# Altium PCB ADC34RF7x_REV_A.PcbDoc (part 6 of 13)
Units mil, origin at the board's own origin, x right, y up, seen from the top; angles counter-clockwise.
Board outline 6250 x 2716.54 mil, 18 copper layers (Top Layer, L2 GND, L3 PWR, L4 GND, L5 PWR/SIG, L6 GND, L7 SIGNAL, L8 GND, L9 GND, L10 SIGNAL, L11 GND, L12 SIGNAL, L13 GND, L14 PWR, L15 GND, L16 PWR/SIG, L16 GND, Bottom Layer), stack 95.314 mil thick; 668 components, 786 nets, 3150 pads, 2020 vias.
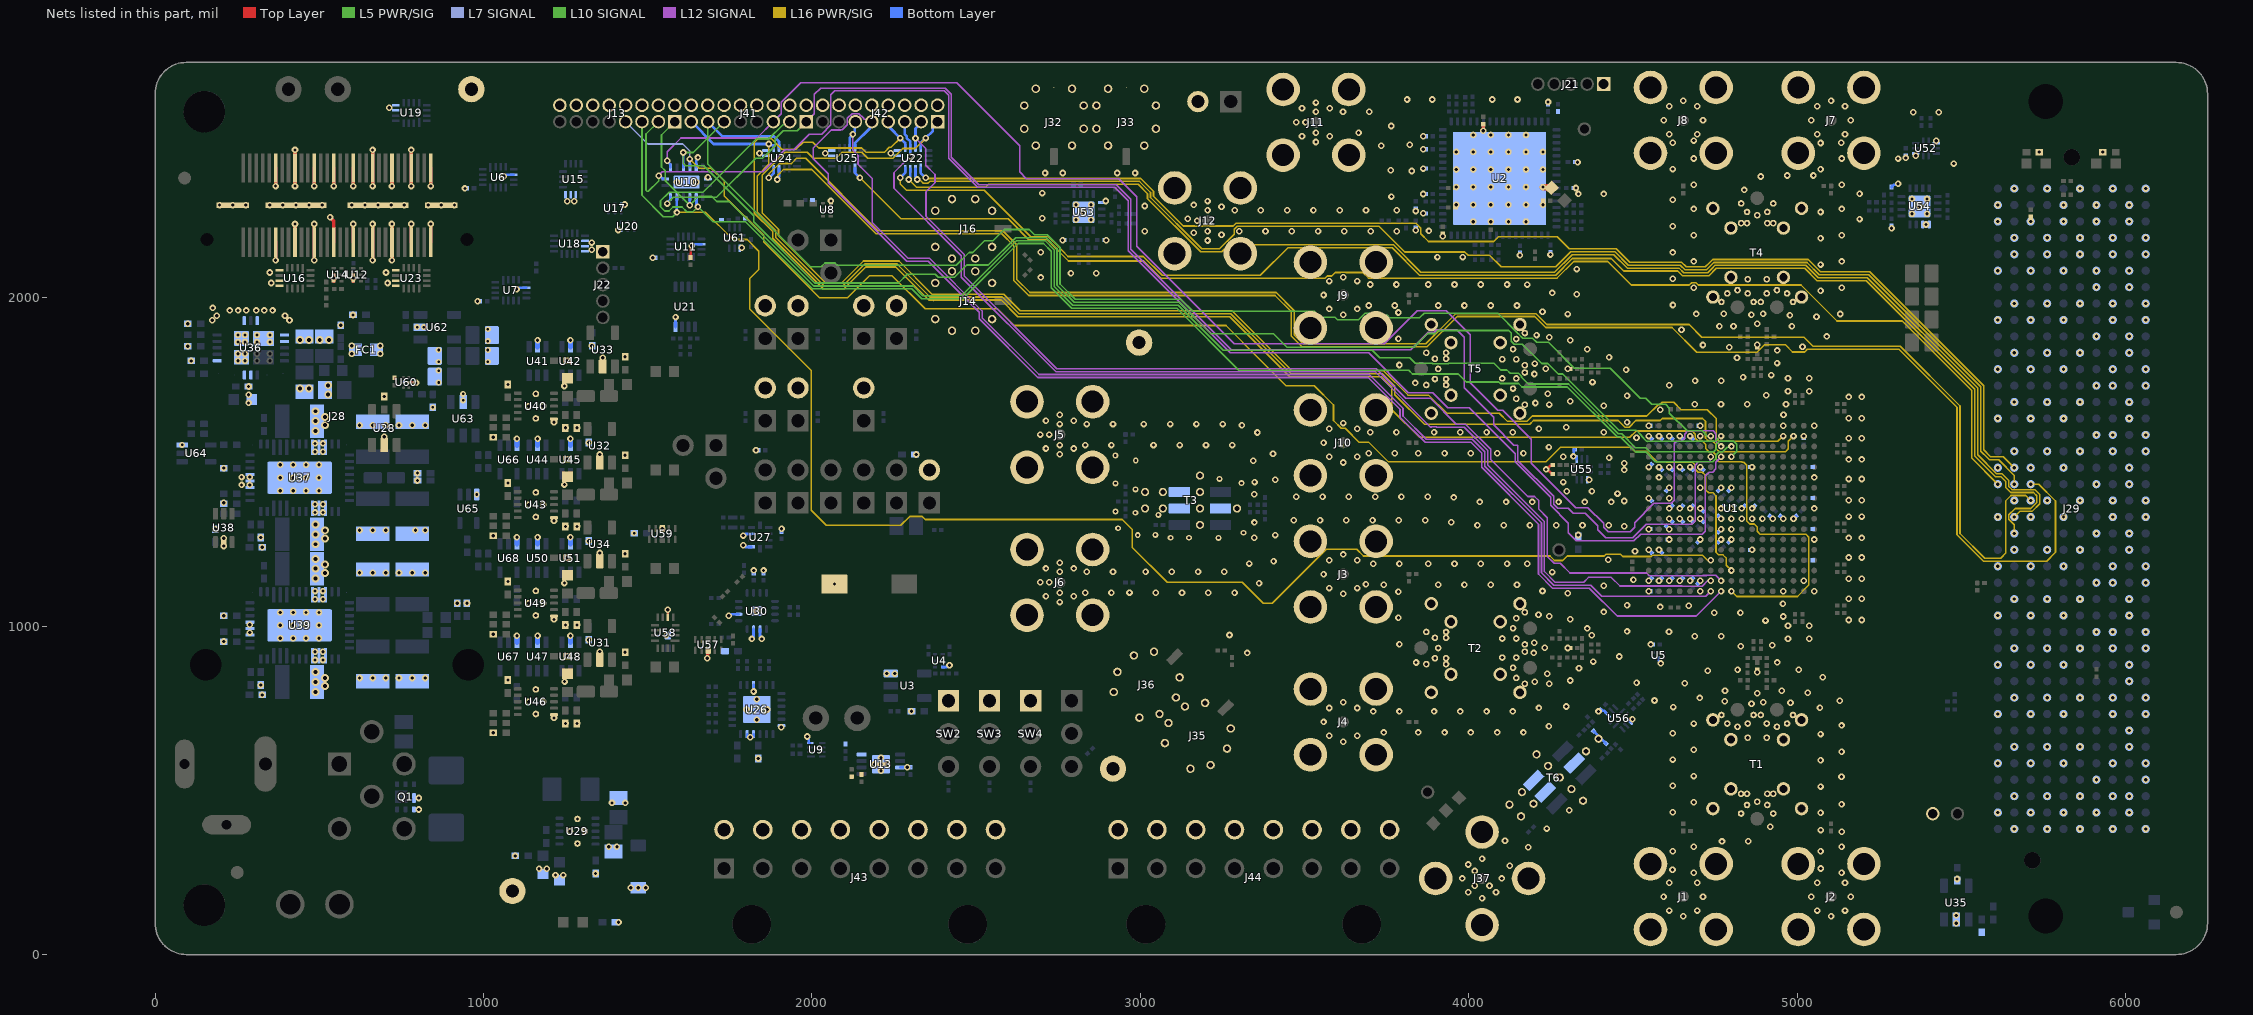
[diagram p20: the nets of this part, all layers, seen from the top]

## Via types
v1: diameter 20, hole 10, Top Layer to Bottom Layer, tented both sides, 1793 vias
v2: diameter 24, hole 12, Top Layer to Bottom Layer, tented both sides, 168 vias
v3: diameter 18, hole 8, Top Layer to Bottom Layer, tented both sides, 59 vias

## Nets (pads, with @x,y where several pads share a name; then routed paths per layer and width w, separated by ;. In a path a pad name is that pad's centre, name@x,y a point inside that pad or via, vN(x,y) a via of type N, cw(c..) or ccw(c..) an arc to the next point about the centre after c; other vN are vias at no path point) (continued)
GND: C5.1 C13.1 C29.1 C37.1 C41.2 C42.2 C43.2 C44.2 C45.2 C46.2 C47.2 C48.2 C49.2 C50.2 C51.2 C52.2 C54.2 C57.1 C58.1 C60.1 C61.1 C62.1 C63.1 C69.1 C72.2 C73.2 C74.1 C92.2 C93.1 C94.2 C95.1 C96.1 C97.1 C98.1 C102.2 C103.2 C104.2 C105.1 C106.2 C107.2 C108.2 C109.2 C110.1 C111.1 C112.1 C113.1 C114.1 C115.1 C116.1 C117.1 C118.1 C119.1 C120.1 C121.1 C122.2 C123.1 C124.2 C125.1 C126.1 C127.1 C128.2 C129.1 C130.2 C131.2 C132.1 C133.1 C134.1 C135.1 C136.1 C137.1 C138.1 C139.1 C140.1 C141.1 C142.1 C143.1 C144.1 C145.1 C146.1 C147.1 C148.1 C149.1 C150.1 C151.1 C152.1 C153.1 C154.1 C155.1 C156.1 C157.1 C158.1 C159.1 C160.1 C161.1 C162.1 C163.1 C164.1 C165.1 C166.1 C167.2 C168.1 C169.1 C170.2 C171.1 C172.1 C173.1 C174.1 C175.2 C176.2 C177.2 C178.1 C179.1 C180.1 C181.1 C182.1 C183.1 C184.1 C185.1 C186.1 C187.1 C188.1 C189.1 C204.1 C205.1 C208.1 C209.1 C213.1 C214.1 C215.1 C216.1 C217.1 C218.1 C221.1 C222.1 C223.1 C224.1 C225.1 C226.1 C227.1 C228.1 C229.1 C230.1 C233.1 C235.1 C236.1 C237.1 C240.1 C242.1 C243.1 C244.1 C247.1 C249.1 C250.1 C251.1 C254.1 C256.1 C258.1 C263.1 C264.1 D5.2 FC1.2 J1.2 J1.3 J1.4 J1.5 J2.2 J2.3 J2.4 J2.5 J3.2 J3.3 J3.4 J3.5 J4.2 J4.3 J4.4 J4.5 J5.2 J5.3 J5.4 J5.5 J6.2 J6.3 J6.4 J6.5 J7.2 J7.3 J7.4 J7.5 J8.2 J8.3 J8.4 J8.5 J9.2 J9.3 J9.4 J9.5 J10.2 J10.3 J10.4 J10.5 J11.2 J11.3 J11.4 J11.5 J12.2 J12.3 J12.4 J12.5 J13.2 J13.4 J13.6 J13.8 J13.10 J13.12 J13.14 J13.16 J14.2 J16.2 J21.1 J22.1 J24.2 J25.2 J26.2 J27.2 J28.1 J28.2 J28.7 J28.8 J28.13 J28.14 J28.19 J28.20 J28.25 J28.26 J28.31 J28.32 J28.37 J28.38 J28.43 J28.44 J28.49 J28.50 J28.MP1 J28.MP2 J28.MP3 J28.MP4 J29.A1 J29.A4 J29.A5 J29.A8 J29.A9 J29.A12 J29.A13 J29.A16 J29.A17 J29.A20 J29.A21 J29.A24 J29.A25 J29.A28 J29.A29 J29.A32 J29.A33 J29.A36 J29.A37 J29.A40 J29.B2 J29.B3 J29.B6 J29.B7 J29.B10 J29.B11 J29.B14 J29.B15 J29.B18 J29.B19 J29.B22 J29.B23 J29.B26 J29.B27 J29.B30 J29.B31 J29.B34 J29.B35 J29.B38 J29.B39 J29.C1 J29.C4 J29.C5 J29.C8 J29.C9 J29.C12 J29.C13 J29.C16 J29.C17 J29.C20 J29.C21 J29.C24 J29.C25 J29.C28 J29.C29 J29.C32 J29.C33 J29.C36 J29.C38 J29.C40 J29.D2 J29.D3 J29.D6 J29.D7 J29.D10 J29.D13 J29.D16 J29.D19 J29.D22 J29.D25 J29.D28 J29.D37 J29.D39 J29.E1 J29.E4 J29.E5 J29.E8 J29.E11 J29.E14 J29.E17 J29.E20 J29.E23 J29.E26 J29.E29 J29.E32 J29.E35 J29.E38 J29.E40 J29.F2 J29.F3 J29.F6 J29.F9 J29.F12 J29.F15 J29.F18 J29.F21 J29.F24 J29.F27 J29.F30 J29.F33 J29.F36 J29.F39 J29.G1 J29.G4 J29.G5 J29.G8 J29.G11 J29.G14 J29.G17 J29.G20 J29.G23 J29.G26 J29.G29 J29.G32 J29.G35 J29.G38 J29.G40 J29.H3 J29.H6 J29.H9 J29.H12 J29.H15 J29.H18 J29.H21 J29.H24 J29.H27 J29.H30 J29.H33 J29.H36 J29.H39 J29.J1 J29.J4 J29.J5 J29.J8 J29.J11 J29.J14 J29.J17 J29.J20 J29.J23 J29.J26 J29.J29 J29.J32 J29.J35 J29.J38 J29.J40 J29.K2 J29.K3 J29.K6 J29.K9 J29.K12 J29.K15 J29.K18 J29.K21 J29.K24 J29.K27 J29.K30 J29.K33 J29.K36 J29.K39 J30.2 J32.2 J33.2 J34.2 J35.2 J36.2 J37.2 J37.3 J37.4 J37.5 J39.2 J40.2 J41.2 J41.4 J41.6 J41.8 J41.10 J41.12 J41.14 J41.16 J42.2 J42.4 J42.6 J42.8 J42.10 J42.12 J42.14 J42.16 J43.2 J43.4 J43.6 J43.8 J43.10 J43.12 J43.14 J43.16 J44.2 J44.4 J44.6 J44.8 J44.10 J44.12 J44.14 J44.16 J45.2 NT8.2 PP2.1 Q1.4 Q1.7 R40.2 R50.2 R52.1 R56.1 R57.1 R65.1 R75.1 R76.1 R77.1 R83.1 R86.1 R87.1 R109.1 R110.1 R111.1 R115.2 R116.1 R117.1 R120.1 R122.1 R124.1 R127.1 R128.1 R130.1 R134.1 R135.1 R140.1 R141.1 R146.1 R147.1 R152.1 R153.1 R163.1 R193.1 R194.1 R195.1 R196.1 R212.2 R213.2 R214.2 R216.1 R226.1 SW1.1 SW2.3 SW3.3 SW4.3 T1.4 T2.4 T3.1 T3.2 T3.5 T4.4 T5.4 T6.1 T6.2 T6.5 TP4.1 TP5.1 TP9.1 TP10.1 U1.A1 U1.A6 U1.A9 U1.A12 U1.A17 U1.B2 U1.B16 U1.C10 U1.D1 U1.D10 U1.D17 U1.E10 U1.F10 U1.G5 U1.G9 U1.G10 U1.G13 U1.H9 U1.H10 U1.J7 U1.J9 U1.J10 U1.J11 U1.J12 U1.K7 U1.K9 U1.K10 U1.K11 U1.K12 U1.M1 U1.M2 U1.M5 U1.M7 U1.M9 U1.M10 U1.M12 U1.M16 U1.M17 U1.N2 U1.N5 U1.N9 U1.N10 U1.N16 U1.P2 U1.P5 U1.P9 U1.P10 U1.P16 U1.R2 U1.R5 U1.R7 U1.R8 U1.R9 U1.R10 U1.R11 U1.R12 U1.R16 U1.T2 U1.T5 U1.T6 U1.T13 U1.T16 U1.U1 U1.U2 U1.U5 U1.U8 U1.U11 U1.U13 U1.U16 U1.U17 U2.65 U3.3 U4.3 U5.B2 U6.6 U7.6 U8.3 U9.4 U10.6 U10.8 U10.17 U11.6 U12.2 U12.3 U13.4 U13.7 U13.9 U14.2 U14.3 U15.6 U15.7 U15.8 U16.5 U16.7 U16.8 U17.3 U18.6 U18.7 U18.8 U19.7 U19.8 U20.3 U21.4 U22.7 U22.8 U23.5 U23.7 U23.8 U24.7 U24.8 U25.7 U25.8 U26.9 U26.18 U26.22 U26.23 U26.25 U27.1 U27.3 U28.2 U29.11 U30.2 U30.3 U30.6 U30.17 U31.2 U32.2 U33.2 U34.2 U35.2 U36.1 U36.2 U36.3 U36.5 U36.6 U36.7 U36.8 U36.9 U36.16 U36.17 U36.20 U36.25 U36.26 U36.28 U37.10 U37.11 U37.12 U37.27 U37.28 U37.29 U37.41 U37.42 U37.43 U37.47 U37.48 U37.49 U37.50 U37.51 U38.2 U39.10 U39.11 U39.12 U39.27 U39.28 U39.29 U39.41 U39.42 U39.43 U39.47 U39.48 U39.49 U39.50 U39.51 U40.6 U40.11 U41.2 U42.2 U43.6 U43.11 U44.2 U45.2 U46.6 U46.11 U47.2 U48.2 U49.6 U49.11 U50.2 U51.2 U52.3 U52.8 U53.1 U53.17 U54.1 U54.2 U54.17 U55.3 U55.8 U56.3 U56.8 U57.3@1684.51,926.32 U58.6 U59.3@1544.55,1296.99 U60.B2 U61.3 U62.2 U63.2 U64.3 U65.3 U66.3 U67.3 U68.3 | length 3247.4
  Top Layer w6.5: U58.6@1561.46,1026.83 v1(1561.46,1049.84)
  Top Layer w8: U60.B2@772.4,1741.98 794.35,1741.98 v1(794.35,1740.63) ; R50.2@1630.62,2122.52 1630.62,2151.78 1633.62,2154.78 v1(1633.62,2158.03) ; U8.3@2057.95,2287.75 v1(2057.97,2294.83) ; U2.65@3962.2,2281.38 3962.3,2281.47 U2.65@3962.3,2283.34 ; U2.65@4226.08,2283.34 4226.41,2283.67 4226.41,2295.11 C73.2@4226.73,2295.44 ; v1(4235.73,1477.13) v1@4237.05,1477.13 ; R193.1@4255.32,1491.24 4255.32,1491.03 4252.73,1488.45 4248.36,1488.45 v1@4237.05,1477.13 ; R194.1@4255.81,1463.74 4253.52,1466.04 4250.07,1466.04 4238.98,1477.13 v1@4237.05,1477.13 ; v1(4301.69,933.31) C13.1@4308.77,933.29 ; v1(4301.69,1783.28) C37.1@4308.77,1783.27 ; v1(4878.51,859.95) C5.1@4878.52,867.04 ; C29.1@4878.54,1849.5 C29.1@4878.54,1856.57 ; v1(5331.02,2425.76) v1@5331.04,2432.84 ; v1(5361.02,2432.05) v1@5361.04,2439.14 ; v1@5424.03,2470.64 v1(5424.05,2477.73) ; v1(5711.42,2232.27) R86.1@5711.42,2246.24
  Top Layer w10: v1(4044.13,2508.75) C47.2@4044.13,2528.75
  Top Layer w11: v1(366.89,2114.41) J28.50@366.89,2169.41 ; v1(366.89,2340) J28.49@366.89,2395 ; J28.44@425.94,2169.41 v1(425.94,2224.41) ; v1(425.94,2340) J28.43@425.94,2395 v1(425.94,2450) ; v1(485,2114.41) J28.38@485,2169.41 v1(485,2224.41) ; v1(485,2340) J28.37@485,2395 ; v1(532.82,2245) 544.06,2233.77 J28.32@544.06,2169.41 ; U14.3@543.54,2050.04 v1(543.54,2059.88) U14.2@543.54,2069.72 ; v1(544.06,2340) J28.31@544.06,2395 ; J28.26@603.11,2169.41 v1(603.11,2224.41) ; v1(603.11,2340) J28.25@603.11,2395 ; U12.3@603.23,2050.04 v1(603.23,2059.88) U12.2@603.23,2069.72 ; v1(662.17,2114.41) J28.20@662.17,2169.41 v1(662.17,2224.41) ; v1(662.17,2340) J28.19@662.17,2395 v1(662.17,2450) ; v1(721.22,2114.41) J28.14@721.22,2169.41 v1(721.22,2224.41) ; v1(721.22,2340) J28.13@721.22,2395 ; J28.8@780.28,2169.41 v1(780.28,2224.41) ; v1(780.28,2340) J28.7@780.28,2395 v1(780.28,2450) ; J28.2@839.33,2169.41 v1(839.33,2224.41) ; v1(839.33,2340) J28.1@839.33,2395
  Top Layer w12: v1(1681.38,902.07) 1682.91,903.6 1682.91,924.72 U57.3@1684.51,926.32
  Top Layer w20: U2.65@4226.08,2336.89 4240.7,2336.89 4243.53,2334.06 4251.66,2334.06 C72.2@4252.35,2334.75
  L16 PWR/SIG w4: v1(4862.99,1358.27) NT8.2@4871.48,1366.75
  Bottom Layer w4: U53.1@2882.43,2289.97 2890.59,2289.97 v1(2895.14,2294.52)
  Bottom Layer w5: v1@4496.28,713.31 v1@4498.57,715.61
  Bottom Layer w6.5: U61.3@1780.22,2150.58 1781.99,2152.36 v1(1786.57,2152.36)
  Bottom Layer w7: v1(1985.66,663.77) 1985.66,660.25 1990.82,655.1 1990.82,644.02 1990.87,643.96 U9.4@1995.42,643.96
  Bottom Layer w8: R65.1@982,1989.25 R65.1@989.07,1989.25 ; v1(1061.98,2370) 1065.23,2370 1070.23,2375 U6.6@1091.98,2375 ; v1(1100.6,2025.75) 1103.85,2025.75 1108.85,2030.75 U7.6@1130.6,2030.75 ; v1(1515,2121.52) R75.1@1522.09,2121.54 ; v1@1641.87,2163.03 U11.6@1663.62,2163.03 ; U10.6@1647.87,2397.2 1647.87,2418.96 1652.87,2423.96 v1(1652.87,2427.2) ; U26.23@1802.75,671.2 1802.75,664.23 1803.48,663.5 1810.3,663.5 v1(1812.59,661.2) 1814.89,663.5 1821.71,663.5 1822.44,664.23 U26.22@1822.44,671.2 ; v1(1822.44,800.81) U26.9@1822.44,820.81 ; C185.1@1823.1,1161.65 v1(1823.1,1169.65) ; v1(1829.71,1535.36) R163.1@1835.71,1535.36 ; C186.1@1852.79,1161.65 v1(1852.79,1169.65) ; C183.1@1907.71,1288.11 v1(1907.71,1296.11) ; U13.7@2268.5,569.69 2268.7,569.89 2289.71,569.89 v1(2289.91,570.09) C181.1@2299.91,570.09 ; U4.3@2398.98,875.43 2410.74,875.43 2415.74,880.43 v1(2418.98,880.43) ; v1(3838.93,2205.07) R77.1@3838.91,2212.16 ; R76.1@3838.91,2264.14 R76.1@3838.91,2271.21 ; v1(3861.82,2256.88) C57.1@3868.91,2256.89 ; C54.2@3861.84,2315.95 C54.2@3868.91,2315.95 ; v1(3861.82,2393.17) C44.2@3868.91,2393.19 ; C45.2@3861.84,2452.24 C45.2@3868.91,2452.24 ; v1(3861.82,2491.6) C46.2@3868.91,2491.61 ; v1(3920.97,2186.89) v1@3920.96,2193.97 ; v1(4156.1,2129.3) C52.2@4156.08,2136.38 ; C49.2@4241.82,2588.93 v1(4241.81,2596.02) ; v1(4248.84,2131.3) C51.2@4248.82,2138.38 ; C48.2@4319.46,2334.13 C48.2@4326.53,2334.13 ; C263.1@4322.59,1538.27 4321.81,1538.27 4319.51,1535.97 4319.51,1520.69 4316.76,1517.95 4316.76,1514.7 4319.06,1512.4 4328.83,1512.4 4328.89,1512.34 U55.8@4328.89,1508.74 ; R40.2@4324.46,2412.87 v1(4331.55,2412.89) ; U55.3@4360.39,1445.75 v1(4367.48,1445.76) ; R195.1@4380.65,679.9 R196.1@4417.85,642.69 ; v1(4395.32,740.25) C264.1@4399.76,740.25 ; v1(4395.32,740.25) C264.1@4400.32,745.27 ; C264.1@4400.32,742.38 4403.77,745.83 4404.13,745.83 4407.58,742.38 4412.12,742.38 U56.8@4418.34,736.16 ; U56.3@4490.68,708.37 v1(4498.68,716.37) 4498.68,718 v1@4499.2,718.53 ; v1(4548.03,1137.8) C148.1@4555.98,1145.75 ; v1(4548.03,1232.28) C153.1@4555.98,1224.31 ; v1(4548.03,1389.76) C140.1@4555.98,1381.81 ; v1(4548.03,1484.25) C163.1@4555.98,1492.21 ; v1(4548.03,1578.74) C162.1@4555.98,1570.79 ; v1(4554.7,944.29) C179.1@4559.7,944.29 ; U5.B2@4578.88,903.54 4579.08,903.34 4579.08,894.93 4584.4,889.61 v1(4584.4,886.36) ; v1(4579.53,1137.8) C149.1@4587.48,1145.75 ; v1(4579.53,1232.28) C155.1@4587.48,1224.31 ; v1(4579.53,1484.25) C137.1@4587.48,1476.3 ; v1(4579.53,1578.74) C161.1@4587.48,1570.79 ; C141.1@4603.07,1303.23 v1(4611.02,1295.28) ; C139.1@4603.07,1413.31 v1(4611.02,1421.26) ; C93.1@4606.3,1263.78 v1(4611.02,1263.78) ; v1(4611.02,1137.8) C150.1@4618.98,1145.75 ; v1(4611.02,1326.77) C143.1@4618.98,1318.82 ; v1(4611.02,1358.27) C138.1@4618.98,1366.22 ; v1(4611.02,1484.25) C136.1@4618.98,1476.3 ; v1(4611.02,1578.74) C160.1@4618.98,1570.79 ; v1(4642.52,1137.8) C151.1@4650.47,1145.75 ; v1(4642.52,1326.77) C144.1@4650.47,1318.82 ; v1(4642.52,1358.27) C147.1@4650.47,1366.22 ; v1(4642.52,1484.25) C135.1@4650.47,1476.3 ; v1(4642.52,1578.74) C159.1@4650.47,1570.79 ; v1(4674.02,1137.8) C152.1@4681.97,1145.75 ; v1(4674.02,1326.77) C145.1@4681.97,1318.82 ; v1(4674.02,1358.27) C146.1@4681.97,1366.22 ; v1(4674.02,1484.25) C134.1@4681.97,1476.3 ; v1(4674.02,1578.74) C158.1@4681.97,1570.79 ; C157.1@4697.56,1129.84 v1(4705.51,1137.8) ; C156.1@4697.56,1255.83 v1(4705.51,1263.78) ; v1(4705.51,1326.77) C117.1@4713.47,1318.82 ; v1(4705.51,1358.27) C116.1@4713.47,1350.31 ; C120.1@4760.55,1255.83 v1(4768.5,1263.78) ; C154.1@4760.55,1287.32 v1(4768.5,1295.28) ; C115.1@4760.55,1334.72 v1(4768.5,1326.77) ; C132.1@4760.55,1413.31 v1(4768.5,1421.26) ; v1(4768.5,1358.27) C114.1@4776.46,1366.22 ; C118.1@4792.05,1255.83 v1(4800,1263.78) ; C133.1@4792.05,1413.31 v1(4800,1421.26) ; v1(4800,1358.27) C113.1@4807.95,1366.22 ; v1(4831.5,1358.27) C105.1@4839.45,1366.22 ; C111.1@4918.03,1334.72 v1(4925.98,1326.77) ; C110.1@4949.53,1334.72 v1(4957.48,1326.77) ; v1(4988.98,1326.77) C121.1@4996.93,1334.72 ; C63.1@5287.73,2337.1 5287.73,2337.89 5290.03,2340.19 5290.81,2340.19 5294.99,2344.36 5305.27,2344.36 v1(5307.57,2346.66) ; v1(5361.02,2432.05) U52.8@5361.04,2439.14 ; U52.3@5424.05,2470.65 v1(5424.05,2477.73) ; v1(4705.51,1484.25) C180.1@4713.47,1476.3 v1(4705.51,1484.25)
  Bottom Layer w9: v1(1747.16,1031.17) 1750.14,1031.17 1755.14,1036.17 U30.6@1777.16,1036.17 ; v1(1790.56,1246.38) 1793.54,1246.38 1798.54,1241.38 U27.1@1815.56,1241.38 ; v1(1790.56,1275.75) 1793.54,1275.75 1798.54,1280.75 U27.3@1815.56,1280.75 ; v1(1817.44,960.89) 1817.44,963.87 1822.44,968.87 U30.3@1822.44,990.89 ; U30.2@1842.12,990.89 1842.12,968.87 1847.12,963.87 v1(1847.12,960.89) ; v1(2763.24,2175.32) C62.1@2768.24,2175.32 ; C61.1@2891.38,2175.32 v1(2896.38,2175.32)
  Bottom Layer w10: v1(1410,2206.18) U20.3@1420,2206.18 ; U17.3@1420,2283.82 v1(1430,2283.82) ; U21.4@1584.81,1911.11 v1(1584.81,1941.11)
  Bottom Layer w15: U67.3@1101.81,950.47 v1(1101.81,970.47) ; U68.3@1101.81,1250.47 v1(1101.81,1270.47) ; U66.3@1101.81,1550.47 v1(1101.81,1570.47) ; U47.2@1164.72,950.47 v1(1164.72,970.47) ; U50.2@1164.72,1250.47 v1(1164.72,1270.47) ; U44.2@1164.72,1550.47 v1(1164.72,1570.47) ; U41.2@1164.72,1850.47 v1(1164.72,1870.47) ; U48.2@1264.72,950.47 v1(1264.72,970.47) ; U51.2@1264.72,1250.47 v1(1264.72,1270.47) ; U45.2@1264.72,1550.47 v1(1264.72,1570.47) ; U42.2@1264.72,1850.47 v1(1264.72,1870.47)
  other v1: 5485,95 1411.26,98.59 4653.52,116.33 5103.52,116.33 5485,119 4611.09,133.9 4695.95,133.9 5061.09,133.9 5145.95,133.9 4040.75,171.61 4593.52,176.33 4713.52,176.33 5043.52,176.33 5163.52,176.33 3998.32,189.19 4083.17,189.19 1448.26,203.39 1471.26,203.39 1494.26,203.39 4018.12,208.99 4063.37,208.99 4611.09,218.75 4695.95,218.75 5061.09,218.75 5145.95,218.75 5487.08,230.01 3980.75,231.61 4100.75,231.61 1219.29,241.95 1242.76,241.95 1341.26,246.68 4685.56,248.58 5135.56,248.58 4018.12,254.24 4620.59,258.45 1169.29,260.73 1192.76,260.73 5071.92,261.92 4124.71,270.27 3998.32,274.04 4040.75,291.61 1096.77,300.1 4621.48,314.81 5071.48,314.81 4181.28,326.84 1381.26,328.55 1406.26,328.55 4685.56,328.58 5135.56,328.58 4771.43,344.29 4851.43,344.67 4110.48,346.65 5135.94,373.77 5071.77,378.9 5661.42,382.27 5761.42,382.27 5861.42,382.27 5961.42,382.27 6061.42,382.27 4237.85,383.4 4918.09,388.91 5071.48,431.36 5611.42,432.27 5711.42,432.27 5811.42,432.27 5911.42,432.27 6011.42,432.27 4621.48,433.59 4306.05,439.54 803.11,441.56 5135.56,457.5 1391.26,461.66 1431.26,461.66 4685.56,463.31 803.11,476.56 5661.42,482.27 5761.42,482.27 5861.42,482.27 5961.42,482.27 6011.42,482.27 5071.48,511.36 4621.48,513.59 5911.42,532.27 6061.42,532.27 5135.17,541.22 4685.56,543.31 5611.42,582.27 5711.42,582.27 5811.42,582.27 5961.42,582.27 6061.42,582.27 5071.48,591.36 4621.48,593.59 1837,596.83 5135.56,617.5 4685.56,623.31 5661.42,632.27 5761.42,632.27 5861.42,632.27 6011.42,632.27 3618.06,648.29 3575.63,665.86 3660.49,665.86 5071.48,671.36 4621.48,673.59 1030,675 3741.26,676.25 3846.62,676.25 3926.62,676.25 4006.62,676.25 4086.62,676.25 4166.62,676.25 6011.42,682.27 1907.08,691.8 4244.32,695.31 5135.56,697.5 1249.61,703.66 1284.61,703.66 4685.56,703.31 3558.06,708.29 1832.28,714.51 1214.61,720.43 5611.42,732.27 5711.42,732.27 5811.42,732.27 5961.42,732.27 6061.42,732.27 2302.99,740.77 3709.16,740.33 3789.16,740.33 3894.52,740.33 3974.52,740.33 4054.52,740.33 4134.52,740.33 1800.78,746.01 1863.78,746.01 3575.63,750.72 3660.49,750.72 4213.81,750.94 5069.65,751.33 4623.02,753.57 4297.33,755.22 4861.08,763.91 4897.19,767.81 4980,767 3618.06,768.29 4779.8,771.11 4565.7,773.48 5129.79,773.05 1832.28,777.5 4703.42,781.29 5661.42,782.27 5761.42,782.27 5861.42,782.27 5961.42,782.27 6061.42,782.27 326.53,790.55 4878.85,795.78 5032.67,797.17 4780.37,803.17 4953.45,803 321.84,820.55 4244.9,824.66 4657.77,825.63 4511.25,827.93 4201.21,830.25 1246.88,831.13 6011.42,832.27 4308.98,834.37 1074.37,835.95 622.67,842 662.67,842 702.67,842 742.67,842 782.67,842 822.67,842 5078.07,843.89 2228,855.57 2252,855.57 4238.88,855 4727.8,864.31 4818.67,867.39 5005.05,866.94 4335.98,871.83 5611.42,882.27 5711.42,882.27 5811.42,882.27 6011.42,882.27 3839.74,889.16 4939.68,889.38 4379.68,892.09 487.01,896.76 511.01,896.76 4458.17,907.54 1253.98,907.95 3326.01,918.41 4198.25,918.41 1431.18,920.24 487.01,921.76 511.01,921.76 1353.85,922.59 5661.42,932.27 5761.42,932.27 5861.42,932.27 5961.42,932.27 6061.42,932.27 4231.5,934.33 4828.7,938.96 4924.61,941.8 3789.02,945.13 4199.68,949 209.01,953.07 1320.5,958.84 4972.22,961.38 5037.22,961.38 4688.76,969.17 4768.76,969.17 3271.56,972.86 4374.7,971.93 1030,975 288.38,980.44 5911.42,982.27 5961.42,982.27 6061.42,982.27 4482.29,983.81 4609.98,983.12 4361.04,993.05 4972.22,1001.38 5037.22,1001.38 1249.61,1003.66 1284.61,1003.66 288.38,1004.44 4903.87,1016.96 5156.89,1018.65 5196.89,1018.65 1214.61,1020.43 4308.98,1020.58 3786.02,1025.07 4244.9,1029.64 4957.48,1029.28 209.01,1031.81 5611.42,1032.27 5711.42,1032.27 5811.42,1032.27 6011.42,1032.27 4212.58,1034.67 4747.43,1040.56 4827.43,1040.56 4410.9,1043.27 1832.28,1046.01 4583.17,1058.5 4670.37,1062.04 4482.29,1063.81 4956.83,1067.73 919.64,1069.8 949.64,1069.8 2755,1073.28 487.01,1081.8 511.01,1081.8 5661.42,1082.27 5761.42,1082.27 5861.42,1082.27 6011.42,1082.27 5156.89,1083.65 5196.89,1083.65 2712.57,1090.85 2797.43,1090.85 3618.06,1098.29 4301.79,1100.26 2755,1101.28 2832.2,1101.24 2912.2,1101.24 3047.04,1101.24 3127.04,1101.24 3207.04,1101.24 2967.05,1102.07 3287.04,1101.94 3786.02,1105.07 487.01,1106.8 511.01,1106.8 4548.03,1106.3 4705.51,1106.3 4957.48,1106.3 5051.97,1106.3 4224.66,1107.04 3575.63,1115.86 3660.49,1115.86 4410.9,1123.27 3741.26,1126.25 3907,1126.25 3987,1126.25 4067,1126.25 4147,1126.25 3687,1127.19 2068.7,1128.15 3361.7,1130.68 1246.5,1131.13 5911.42,1132.27 5961.42,1132.27 6061.42,1132.27 2695,1133.28 2723,1133.28 1074.37,1135.95 5020.47,1137.8 4501.74,1141.42 5156.89,1144.04 5196.89,1144.04 3558.06,1158.29 622.67,1162.56 662.67,1162.56 702.67,1162.56 742.67,1162.56 782.67,1162.56 822.67,1162.56 4254.35,1164.67 2755,1165.28 2836.8,1165.32 2916.8,1165.32 3016.03,1165.32 3096.03,1165.32 3176.03,1165.32 3256.03,1165.32 2712.57,1175.71 2797.43,1175.71 5611.42,1182.27 5711.42,1182.27 5811.42,1182.27 5961.42,1182.27 6061.42,1182.27 3332,1190.39 3709.16,1190.33 3789.16,1190.33 3876.79,1190.33 3956.79,1190.33 4036.79,1190.33 4116.79,1190.33 4178.47,1190.02 2755,1193.28 3405.93,1197.34 3575.63,1200.72 3660.49,1200.72 4425.02,1202.02 1253.98,1207.95 5156.89,1209.04 5196.89,1209.04 3618.06,1218.29 1431.18,1220.24 1353.85,1222.59 4506.5,1228.35 4862.99,1232.28 5661.42,1232.27 5761.42,1232.27 5861.42,1232.27 6011.42,1232.27 326.53,1240.04 209.01,1243.95 1320.5,1258.84 5051.97,1263.78 209.01,1267.95 5156.89,1268.52 5196.89,1268.52 3347.24,1268.93 321.84,1270.04 1030,1275 3411.32,1277.16 4333.91,1277.56 5911.42,1282.27 6011.42,1282.27 622.67,1291.5 662.67,1291.5 702.67,1291.5 792.67,1291.5 822.67,1291.5 183.42,1295.32 4548.03,1295.28 4800,1295.28 1544.55,1296.99 1249.61,1303.66 1284.61,1303.66 4473.75,1304.02 4026.57,1306.82 4106.57,1306.82 4186.57,1306.82 4266.57,1306.82 4346.57,1306.82 4426.57,1306.82 3347.64,1315.8 3947.17,1316.58 1214.61,1320.43 3467.4,1322.58 3547.4,1322.58 3627.4,1322.58 3707.4,1322.58 3787.4,1322.58 3867.4,1322.58 4800,1326.77 4831.5,1326.77 4862.99,1326.77 4894.49,1326.77 5611.42,1332.27 5711.42,1332.27 5811.42,1332.27 5961.42,1332.27 6061.42,1332.27 5156.89,1333.52 5196.89,1333.52 487.01,1346.25 511.01,1346.25 5051.97,1358.27 487.01,1371.25 511.01,1371.25 209.01,1375.56 4033.78,1378.21 4113.78,1378.21 4193.78,1378.21 4273.78,1378.21 4353.78,1378.21 4433.78,1378.21 4473.75,1381.02 5661.42,1382.27 5761.42,1382.27 5861.42,1382.27 5961.42,1382.27 6061.42,1382.27 5156.89,1383.01 5196.89,1383.01 4611.02,1389.76 3954.38,1391.97 3475.09,1393.97 3555.09,1393.97 3635.09,1393.97 3715.09,1393.97 3795.09,1393.97 3875.09,1393.97 3347.41,1401.33 4453.19,1403.53 4298.27,1410.62 4375.27,1410.62 4705.51,1421.26 263.38,1429.93 288.38,1429.93 1246.5,1431.13 5911.42,1432.27 6011.42,1432.27 1074.37,1435.95 3347.94,1438.63 4287.86,1438.75 798.85,1443.41 3411.32,1445.57 5156.89,1448.01 5196.89,1448.01 4579.53,1452.76 5051.97,1452.76 263.38,1453.93 288.38,1453.93 798.85,1466.04 4473.75,1475.51 209.01,1481.3 5611.42,1482.27 5711.42,1482.27 5811.42,1482.27 6011.42,1482.27 4862.99,1484.25 4473.75,1495.84 3618.06,1498.27 3344.17,1503.5 5156.89,1507.5 5196.89,1507.5 1253.98,1507.95 4427.37,1512.45 3575.63,1515.84 3660.49,1515.84 4287.86,1515.74 4318.99,1516.77 1431.18,1520.24 1353.85,1522.59 2317.76,1522.61 2755,1523.28 3404.14,1525.25 3695.26,1526.23 3775.26,1526.23 3846.62,1526.23 3926.62,1526.23 4006.62,1526.23 4086.62,1526.23 4166.62,1526.23 487.01,1531.29 511.01,1531.29 5661.42,1532.27 5761.42,1532.27 5861.42,1532.27 5961.42,1532.27 6061.42,1532.27 2712.57,1540.85 2797.43,1540.85 4244.32,1545.29 2755,1551.28 2832.2,1551.24 2912.2,1551.24 3040.1,1551.24 3120.1,1551.24 3200.1,1551.24 3280.1,1551.4 487.01,1556.29 511.01,1556.29 1320.5,1558.84 3558.06,1558.27 5156.89,1572.5 5196.89,1572.5 4511.06,1573.28 1030,1575 698.02,1576.55 4705.51,1578.74 5020.47,1578.74 5911.42,1582.27 5961.42,1582.27 6061.42,1582.27 2695,1583.28 2723,1583.28 3356.69,1589.66 3699.86,1590.31 3779.86,1590.31 3894.52,1590.31 3974.52,1590.31 4054.52,1590.31 4134.52,1590.31 4410.9,1590.74 3575.63,1600.69 3660.49,1600.69 4213.81,1600.92 1249.61,1603.66 1284.61,1603.66 4297.33,1605.2 4548.03,1610.24 4705.51,1610.24 4957.48,1610.24 5051.97,1610.24 3309.42,1611.84 622.67,1612.05 662.67,1612.05 702.67,1612.05 742.67,1612.05 782.67,1612.05 822.67,1612.05 2755,1615.28 2836.8,1615.32 2916.8,1615.32 3010.89,1615.32 3090.89,1615.32 3170.89,1615.32 3250.89,1615.32 3618.06,1618.27 1214.61,1620.43 4482.29,1621.1 2712.57,1625.71 2797.43,1625.71 5156.89,1632.89 5196.89,1632.89 5611.42,1632.27 5711.42,1632.27 5811.42,1632.27 6011.42,1632.27 2755,1643.28 4958.59,1643.27 4583.17,1658.62 4410.9,1670.74 4244.9,1674.63 4688.33,1675.98 4768.33,1675.98 4848.33,1675.98 4966.23,1676 284.57,1679.64 4203.21,1679.47 5661.42,1682.27 5761.42,1682.27 5861.42,1682.27 6011.42,1682.27 4308.98,1684.35 5156.89,1697.89 5196.89,1697.89 697.55,1699.25 4482.29,1701.1 4906.19,1702.6 284.57,1704.64 4240.88,1707.41 4972.22,1715.16 5037.22,1715.16 284.56,1729.64 1246.5,1731.13 5911.42,1732.27 5961.42,1732.27 6061.42,1732.27 4610.5,1733.8 1074.37,1735.95 3837.35,1740.47 4376.91,1743.16 4689.34,1747.37 4769.34,1747.37 4972.22,1755.16 5037.22,1755.16 4835.47,1757.92 4921.48,1764.38 4200.21,1767.78 4479.28,1781.05 5611.42,1782.27 5711.42,1782.27 5811.42,1782.27 5961.42,1782.27 6061.42,1782.27 4234.52,1784.09 3789.02,1795.11 4200.97,1799.43 4939,1801 109.72,1807.64 1253.98,1807.95 1362.85,1817.59 4817,1817 4427.41,1818.32 1431.18,1820.24 5661.42,1832.27 5761.42,1832.27 5861.42,1832.27 6011.42,1832.27 4939.29,1839.59 4361.04,1843.03 4793.01,1849.29 5016.48,1850.4 99.72,1852.01 1329.5,1853.84 4713.3,1856.03 4878.56,1856.58 4308.98,1870.56 3786.02,1875.05 4244.9,1879.62 5089.93,1882.12 5911.42,1882.27 6011.42,1882.27 4206.72,1886.36 4648.06,1902.33 4763.57,1913.37 4806.43,1913.4 4984.39,1913.37 565.28,1916.41 99.72,1920.69 4878.76,1920.76 173.74,1931.63 409.17,1931.63 5611.42,1932.27 5711.42,1932.27 5811.42,1932.27 5961.42,1932.27 6061.42,1932.27 5059.12,1941.92 187.46,1945.35 395.45,1945.35 4978.11,1946.7 602.56,1947.48 3618.06,1948.27 4860.87,1948.21 4301.79,1950.24 4692.84,1950.74 5131.42,1950.52 4777,1951.11 4896.51,1951.36 3786.02,1955.05 4224.66,1957.02 227.63,1961.4 252.63,1961.4 277.63,1961.4 307.63,1961.4 332.63,1961.4 357.63,1961.4 3575.63,1965.84 3660.49,1965.84 175.65,1969.02 3695.26,1976.23 3775.26,1976.23 3907,1976.23 3987,1976.23 4067,1976.23 4147,1976.23 4621.87,1977.92 5661.42,1982.27 5761.42,1982.27 5861.42,1982.27 5961.42,1982.27 6061.42,1982.27 981.98,1989.24 3558.06,2008.27 4328.98,2010.16 4254.35,2014.65 5071.51,2020.96 4685.58,2030.41 5135.58,2030.41 5911.42,2032.27 6011.42,2032.27 3699.86,2040.31 3779.86,2040.31 3876.79,2040.31 3956.79,2040.31 4036.79,2040.31 4116.79,2040.31 4178.47,2040 353.49,2044.8 707.82,2044.8 3575.63,2050.69 3660.49,2050.69 4621.51,2057.92 2696.98,2061.86 3618.06,2062.27 2788.81,2074.45 2865.81,2074.45 348.84,2076.86 703.17,2076.86 5611.42,2082.27 5711.42,2082.27 5811.42,2082.27 5911.42,2082.27 6011.42,2082.27 4328.98,2087.16 5071.51,2100.96 4685.58,2110.41 5135.58,2110.41 3904.79,2123.77 3981.79,2123.77 5661.42,2132.27 5761.42,2132.27 5861.42,2132.27 5961.42,2132.27 6061.42,2132.27 2696.98,2138.86 4621.51,2137.92 1329.38,2146.38 1329.38,2167.87 3204.82,2174.21 5071.51,2180.96 5661.42,2182.27 5761.42,2182.27 5861.42,2182.27 5961.42,2182.27 6061.42,2182.27 4685.58,2190.41 5135.58,2190.41 3247.24,2191.78 3162.39,2197.78 3013.3,2202.24 3204.82,2202.21 3301.32,2202.17 3381.32,2202.17 3461.32,2202.17 3541.32,2202.17 3621.32,2202.17 3701.32,2202.17 3781.32,2202.17 3878.84,2203.42 5287.74,2211.87 4621.51,2217.92 5392.53,2223 5611.42,2232.27 5811.42,2232.27 5911.42,2232.27 6011.42,2232.27 3172.82,2234.21 5190.37,2239.53 3144.82,2240.21 2701.33,2241.62 5071.51,2260.96 3838.93,2264.13 3204.82,2266.21 3287.22,2266.24 3367.22,2266.24 3447.22,2266.24 3527.22,2266.24 3607.22,2266.24 3687.22,2266.24 3781.32,2266.25 4685.58,2270.41 5135.58,2270.41 3247.24,2276.63 3013.3,2279.24 196.38,2282.2 236.38,2282.2 276.38,2282.2 348.9,2282.2 388.9,2282.2 428.9,2282.2 468.9,2282.2 508.9,2282.2 598.9,2282.2 638.9,2282.2 678.9,2282.2 718.9,2282.2 758.9,2282.2 831.42,2282.2 871.42,2282.2 911.42,2282.2 3162.39,2282.63 5611.42,2282.27 5811.42,2282.27 5911.42,2282.27 6011.42,2282.27 1254.74,2293.39 1276.23,2293.39 3204.82,2294.21 4621.51,2297.92 3764.61,2308.12 3861.82,2315.93 4334.07,2316.12 4411.07,2316.12 5190.37,2316.53 2701.33,2318.62 4839.13,2328.2 943.36,2332.72 5661.42,2332.27 5761.42,2332.27 5861.42,2332.27 5961.42,2332.27 6061.42,2332.27 4326.55,2334.15 4685.58,2343.87 5136.12,2343.88 1683.31,2366.77 4889.71,2369.12 4969.65,2372.24 5049.65,2372.24 2710,2379.71 2764,2379.71 2930,2379.71 2984,2379.71 3826.99,2385.88 3763.02,2388.11 4621.51,2391.77 5071.51,2391.04 5476.63,2408.51 4685.58,2423.87 5135.58,2423.87 5307.57,2423.66 1840.38,2440.31 2040.38,2440.31 2240.38,2440.31 5737.73,2443.51 5931.1,2443.52 3861.82,2452.23 3734.13,2462.71 3820.34,2465.61 4621.51,2471.77 5071.51,2471.04 5134.36,2471.77 3534.82,2474.21 4685.31,2478.62 3492.39,2491.78 3577.24,2491.78 4611.12,2497.78 4695.97,2497.78 5061.12,2497.78 5145.97,2497.78 3534.82,2502.21 3664.57,2502.22 3764.46,2522.85 3474.82,2534.21 3502.82,2534.21 4593.54,2540.21 4713.54,2540.21 5043.54,2540.21 5163.54,2540.21 5354.04,2564.64 5431.03,2564.64 3534.82,2566.21 3617.22,2566.19 3697.22,2566.19 3492.39,2576.63 3577.24,2576.63 713.03,2578.31 4611.12,2582.63 4695.97,2582.63 5061.12,2582.63 5145.97,2582.63 3534.82,2594.21 4653.54,2600.21 5103.54,2600.21 3812.35,2603.54 3889.35,2603.54 4071.71,2603.54 4148.71,2603.54
  other v2: 487.86,799.76 517.86,817.26 487.86,829.76 517.86,842.26 487.86,859.76 487.86,1144.8 517.86,1162.3 487.86,1174.8 517.86,1187.3 487.86,1204.8 487.86,1249.25 517.86,1266.75 487.86,1279.25 517.86,1291.75 487.86,1309.25 487.86,1594.29 517.86,1611.79 487.86,1624.29 517.86,1636.79 487.86,1654.29 527.13,1705.75 441.38,1723.62 468.94,1723.62 527.13,1733.3 441.38,1871.73 468.94,1871.73 501.38,1871.73 528.94,1871.73
  other v3: 1556.46,971.72 3237.98,1268.73 3092.32,1269.11 3148.12,1269.11 2992.14,1277.26 3045.86,1277.68 1458.82,1282.81 3314.36,1284.25 2932.3,1297.94 3054.98,1338.87 2984.96,1345.29 2924.5,1349.04 979.49,1400.62 2985.55,1416.28 2924.36,1434.78 3308.14,1435.19 3241.32,1448.2 2986.02,1504.28 2924.22,1519.56 82.39,1551.77 845.87,1666.29 937.99,1687.4 937.99,1707.4 863.37,1741.9 863.37,1777.9 863.37,1804.9 1013.48,1804.9 863.37,1840.9 1013.48,1840.9 1013.48,1867.9 1013.48,1903.9 798.07,1910.3 818.07,1910.3
GPIO0_ADC: J13.1 U1.J4 U10.12 | length 4131.8
  L10 SIGNAL w4: 4539,1543.33 4551.09,1531.24 4746.01,1531.24 4753.5,1538.74 4753.5,1553.46 4762.79,1562.74 4784.46,1562.74 4784.96,1563.24 4806.63,1563.24 4816,1553.87 4816,1531.75 v1(4800,1515.75)
  L10 SIGNAL w5: J13.1@1582.61,2536.06 1542.2,2495.65 1542.2,2398.07 1553.66,2386.61 1553.66,2356.18 v1(1628.19,2281.65) 1656,2309.46 1693.62,2309.46 1710.24,2292.85 1748.38,2292.85 2005.36,2035.86 2307.66,2035.86 2337.9,2005.62 2455.72,2005.62 2624.1,2174 2709.64,2174 2737.46,2146.19 2737.46,2034.5 2794.71,1977.25 3115.25,1977.25 3252.21,1840.29 3310.4,1840.29 3706.22,1840.29 3729.51,1817 3730.21,1817 3820.34,1817 3836.82,1800.52 3888.93,1800.52 3890.69,1798.77 3937.53,1798.77 3939.28,1800.52 4077.07,1800.52 4097.71,1779.88 4116.4,1779.88 4126.51,1769.77 4151.53,1769.77 4160.61,1760.69 4160.61,1758.23 4181.54,1737.3 4304.09,1737.3 4401.44,1639.95 4455.75,1585.64 4465.65,1585.64 4507.96,1543.33 4539,1543.33
  Bottom Layer w8: v1(1628.19,2281.65) U10.12@1628.19,2306.65
GPIO1_ADC: J13.3 U1.K4 U10.1 | length 4747.1
  L5 PWR/SIG w5: J13.3@1532.61,2536.06 1494.97,2498.42 1494.97,2327 1497.9,2324.07 1502.04,2324.07 1533.39,2355.41 v1(1533.39,2371.77)
  L12 SIGNAL w4: v1(1533.39,2371.77) 1544.56,2382.95 1850.97,2382.95 1918.02,2450 1944.59,2450 1992.48,2497.89 2029.47,2497.89 2057.86,2526.28 2057.86,2618.35 2070.04,2630.53 2402.48,2630.53 2417,2616.01 2417,2424 2504.38,2336.62 2921.73,2336.62 2962.67,2295.69 2962.67,2143.33 3273.73,1832.27 3694.92,1832.27 3816,1711.19 3890.7,1711.19 3936.47,1665.42 4001.15,1665.42 4141.02,1525.55 4141.02,1500.34 4249.28,1392.08 4249.28,1367.36 4303.66,1312.98 4303.66,1283.83 4327.86,1259.62 4502.57,1259.62 4523.25,1280.3 4541.79,1280.3 4711.73,1280.28 4721.01,1289.56 4721.01,1457.97 4731.79,1468.75 4742.72,1468.75 4752.5,1478.53 4752.5,1499.75 v1(4768.5,1515.75)
  Bottom Layer w8: v1(1533.39,2371.77) 1536.3,2371.77 1546.3,2361.77 U10.1@1553.39,2361.77
GPIO2_ADC: J13.5 U1.L14 U10.14 | length 4598.3
  L16 PWR/SIG w5: v1(1589.02,2259.8) 1677.22,2259.8 1759.69,2177.33 1802.69,2177.33 1838.36,2141.66 1838.36,2086.1 1810.81,2058.55 1810.81,1965.44 1997.94,1778.31 1997.94,1352.87 2043.98,1306.83 2270.95,1306.83 2297.98,1333.86 2335.64,1333.86 2344.82,1324.69 2890.81,1324.69 2945.31,1324.69 2975,1295 2975,1240.5 ; 2975.25,1240.25 2975,1240.5 ; v1(4737.01,1200.76) 4727.43,1200.76 4711.93,1216.26 4560.76,1216.26 4556.35,1211.85 4469.09,1211.85 4462.43,1218.52 4418.19,1218.52 4412.99,1213.32 4300.05,1213.32 4286.55,1199.82 4261.28,1199.82 4247.78,1213.32 3679.45,1213.32 3658.98,1233.79 3565.9,1233.79 3401.4,1069.29 3374.43,1069.29 3310.44,1133.28 3082.22,1133.28 2975,1240.5
  L5 PWR/SIG w5: J13.5@1482.61,2536.06 1482.61,2312.14 1547.8,2246.96 1576.17,2246.96 v1(1589.02,2259.8)
  Bottom Layer w8: U10.14@1588.82,2306.65 1588.09,2305.93 1588.09,2260.73 v1(1589.02,2259.8)
GPIO3_ADC: J13.7 U1.J15 U10.5 | length 4276
  L16 PWR/SIG w5: v1(1628.19,2422.2) 1656.2,2394.2 1693.94,2394.2 1732.62,2355.52 1732.62,2310.99 1853.39,2190.21 1853.39,2169.58 2023.11,1999.86 2108.64,1999.86 2175.51,2066.73 2244.03,2066.73 2344.76,1966 2565.1,1966 2615.9,1915.2 3260.76,1915.2 3361.7,1814.27 3443.86,1732.11 3529.81,1732.11 3588.48,1673.44 3588.48,1625.93 3611.64,1602.77 3623.77,1602.77 3667.12,1559.42 3696.13,1559.42 3754.52,1501.03 4236.08,1501.03 4279.29,1544.24 4492.72,1544.24 4505.44,1531.52 4541.83,1531.52 4573.11,1500.25 4600.5,1500.25 4601,1499.75 4680.44,1499.75 4689.83,1490.36 4689.83,1478.02 4699.22,1468.63 4711.56,1468.63 4721.26,1458.93 4721.26,1415.09 4730.59,1405.76 4743.75,1405.76 4753,1396.51 4753,1225.35 4761.57,1216.78 4774.4,1216.78 4784,1207.18 4784,1185.29 v1(4800,1169.29)
  L7 SIGNAL w5: J13.7@1432.61,2536.06 1500.49,2468.19 1606.56,2468.19 1628.19,2446.56 v1(1628.19,2422.2)
  Bottom Layer w8: U10.5@1628.19,2397.2 v1(1628.19,2422.2)
GPIO8_ADC: J41.1 U1.L4 U10.15 | length 4574.5
  L5 PWR/SIG w5: v1(1559.13,2286.65) 1578.11,2305.63 1709.61,2305.63 1828.79,2424.81 1849.69,2424.81 1888.1,2463.22 1888.1,2484.12 1912.87,2508.89 1955.45,2508.89 J41.1@1982.62,2536.06
  L12 SIGNAL w4: J41.1@1982.62,2536.06 2007.39,2560.82 2007.39,2619.32 2026.59,2638.53 2405.79,2638.53 2425,2619.32 2425,2427.31 2507.69,2344.62 2926.46,2344.62 2971.67,2299.42 2971.67,2147.06 3277.46,1841.27 3822.81,1841.27 3876.81,1895.27 3895.63,1895.27 3902.7,1902.34 3963.61,1902.34 3986.61,1879.34 3986.61,1725.32 4065.68,1646.25 4075.56,1636.37 4075.56,1613.37 4137.94,1550.99 4150.02,1550.99 4150.02,1504.07 4258.28,1395.81 4258.28,1371.79 4271.17,1358.9 4302.61,1358.9 4318.54,1342.97 4355.56,1342.97 4393.07,1305.46 4393.07,1292.95 4417.4,1268.62 4498.84,1268.62 4540.99,1310.78 4679.94,1310.78 4689.52,1320.35 4689.52,1490.18 4699.59,1500.25 4731.9,1500.25 4734.83,1503.18 4734.83,1513.57 v1(4737.01,1515.75)
  Bottom Layer w8: v1(1559.13,2286.65) 1559.13,2289.57 1569.13,2299.57 U10.15@1569.13,2306.65
GPIO9_ADC: J41.3 U1.J3 U10.11 | length 4378.2
  L5 PWR/SIG w5: v1(1652.87,2276.65) 1638.21,2261.99 1618.74,2261.99 1604.43,2276.3 1577.15,2276.3 1565.09,2264.24 1551.6,2264.24 1539.06,2276.78 1539.06,2294.89 1565.34,2321.16 1668.63,2321.16 1831.15,2483.69 1868.67,2483.69 1911.91,2526.93 1913.66,2526.93 1922.79,2536.06 J41.3@1932.62,2536.06
  L10 SIGNAL w4: 4539,1530.29 4568.54,1500.75 4743.22,1500.75 4753.13,1510.66 4753.13,1521.59 4763.04,1531.5 4773.97,1531.5 4787.54,1545.07 4797.83,1545.07 v1(4800,1547.24)
  L10 SIGNAL w5: v1(1652.87,2276.65) 1697.7,2231.83 1796.66,2231.83 2001.63,2026.86 2303.93,2026.86 2334.17,1996.62 2459.45,1996.62 2627.83,2165 2705.08,2165 2728.46,2141.62 2728.46,2030.78 2790.98,1968.25 3111.53,1968.25 3300.17,1779.61 3817.22,1779.61 3829.06,1767.77 3968.34,1767.77 3992.95,1743.16 4091.3,1743.16 4095.69,1738.77 4151.63,1738.77 4162.1,1728.3 4300.36,1728.3 4452.02,1576.64 4461.92,1576.64 4484.38,1554.19 4508.28,1530.29 4539,1530.29
  Bottom Layer w8: U10.11@1647.87,2306.65 1648.6,2305.93 1648.6,2284.18 1652.87,2279.9 v1(1652.87,2276.65)
GPIO10_ADC: J41.5 U1.K3 U10.2 | length 4566.8
  L12 SIGNAL w4: J41.5@1882.62,2536.06 1907.39,2560.82 1907.39,2595.84 1966.07,2654.53 2440.47,2654.53 2491.06,2603.94 2632.26,2462.74 2632.26,2382.95 2653.08,2362.12 2934.42,2362.12 2989.67,2306.87 2989.67,2156.42 3286.82,1859.27 3742.69,1859.27 3843.31,1959.9 3931.5,1959.9 4004.61,1886.79 4004.61,1740.59 4088.24,1656.96 4103.57,1656.96 4191.12,1569.41 4191.12,1495.85 4326,1360.97 4363.02,1360.97 4411.07,1312.92 4411.07,1300.4 4424.85,1286.62 4491.38,1286.62 4505.53,1300.77 4505.53,1315.23 4564.07,1373.77 4616.95,1373.77 4626.52,1383.34 4626.52,1556.35 4633.42,1563.24 4648.94,1563.24 4658.27,1572.57 4658.27,1584.91 4667.6,1594.24 4744.92,1594.24 4753,1586.16 4753,1562.74 v1(4768.5,1547.24)
  L12 SIGNAL w5: v1(1559.13,2417.2) 1559.13,2444.4 1601.1,2486.37 1832.93,2486.37 J41.5@1882.62,2536.06
  Bottom Layer w8: v1(1559.13,2417.2) 1559.13,2415.79 1568.41,2406.52 1568.41,2397.93 U10.2@1569.13,2397.2
GPIO13_ADC: J41.11 U1.K2 U10.4 | length 4014.9
  L5 PWR/SIG w5: v1(1608.5,2442.2) 1638.76,2442.2 J41.11@1732.62,2536.06
  L10 SIGNAL w4: 4543.29,1562.27 4597.92,1562.27 ; 4597.94,1562.24 4750.98,1562.24 4760.47,1571.74 4761.5,1571.74 v1(4768.5,1578.74)
  L10 SIGNAL w5: v1(1608.5,2442.2) 1608.5,2408.62 1615.52,2401.61 1670.39,2401.61 1822.83,2249.17 1822.83,2231.12 2000.28,2053.67 2009.09,2044.86 2263.87,2044.86 2290.64,2071.64 2375.42,2071.64 2384.99,2062.06 2434.21,2062.06 2471.86,2099.71 2489.34,2099.71 2489.44,2099.81 2505.49,2099.81 2505.58,2099.71 2537.08,2099.71 2620.37,2183 2713.37,2183 2746.46,2149.92 2746.46,2038.23 2798.44,1986.25 3118.98,1986.25 3215.46,1889.77 3406.23,1889.77 3446.71,1849.29 3832.95,1849.29 3874.92,1891.27 3897.29,1891.27 3906.07,1900.05 4122.27,1900.05 4129.61,1892.71 4129.61,1867.85 4138.69,1858.77 4163.55,1858.77 4222.73,1799.59 4240.94,1799.59 4272.74,1767.78 4286.34,1767.78 4457.19,1596.93 4509.34,1596.93 4526.56,1579.71 4526.56,1578.29 4541.61,1563.24 4542.32,1563.24 4543.29,1562.27
  Bottom Layer w8: U10.4@1608.5,2397.2 v1(1608.5,2442.2)
GPIO14_ADC: J41.13 U1.L2 U24.10 | length 3990
  L10 SIGNAL w4: 4557.3,1675.4 4599.65,1675.4 4611.12,1663.94 4611.12,1648.25 4664.88,1594.49 4710.98,1594.49 4726.73,1578.74 v1(4737.01,1578.74)
  L10 SIGNAL w5: J41.13@1682.62,2536.06 1682.62,2407.37 1995.72,2094.27 2028.07,2094.27 2039.66,2105.86 2070.39,2105.86 2077.45,2098.81 2439.72,2098.81 2478.62,2137.7 2489.85,2137.7 2525.29,2173.14 2551.38,2173.14 2586.06,2207.82 2662.26,2207.82 2678.08,2192 2717.1,2192 2755.46,2153.64 2755.46,2041.96 2802.16,1995.25 3122.71,1995.25 3159.36,1958.6 3529.91,1958.6 3547.48,1941.02 3592.5,1941.02 3600.76,1932.77 3664.22,1932.77 3683.69,1952.23 3736.27,1952.23 3741.65,1946.86 3751.68,1946.86 3758.99,1939.55 3851.35,1939.55 3864.66,1952.86 4088.99,1952.86 4148.27,1893.58 4148.27,1892.7 4151.2,1889.77 4151.53,1889.77 4164.53,1876.77 4194.39,1876.77 4207.04,1864.12 4242.77,1864.12 4321.8,1785.09 4430.87,1785.09 4522.24,1693.71 4539,1693.71 4557.3,1675.4
  Bottom Layer w8: J41.13@1682.62,2536.06 1727.62,2491.06 1883.94,2491.06 1899.75,2475.25 U24.10@1899.75,2456.06
GPIO14_FPGA: J29.H19 U24.3 | length 5129.9
  L16 PWR/SIG w5: v1(1894.75,2360.04) 1896.35,2361.63 1896.35,2373.19 1913.7,2390.54 1999.74,2390.54 2195.18,2195.1 2577.72,2195.1 2615.15,2157.67 2615.15,2051.82 2660.16,2006.81 3410.28,2006.81 3460.19,1956.89 3460.19,1882.63 3492.27,1850.55 3872.79,1850.55 3964.98,1942.73 4200.83,1942.73 4234.29,1909.27 4619.19,1909.27 4694.67,1833.79 4877.69,1833.79 4900.48,1856.58 4964.56,1856.58 4986.24,1834.9 5022.9,1834.9 5031.27,1843.27 5310.5,1843.27 5487,1666.77 5487,1278.38 5567.61,1197.77 5759.84,1197.77 5786.92,1224.85 5786.92,1381.28 5735.93,1432.27 v1(5711.42,1432.27)
  Bottom Layer w8: v1@1899.75,2368.28 U24.3@1899.75,2393.07
GPIO15_ADC: J41.15 U1.C2 U24.9 | length 4144.5
  L16 PWR/SIG w5: v1(1869,2468.19) 1869,2406.22 1833.27,2370.49 1833.27,2261.24 1887.28,2207.24 1889.39,2205.13 1889.39,2184.5 2038.02,2035.86 2093.73,2035.86 2160.59,2102.73 2258.94,2102.73 2359.67,2002 2580.01,2002 2630.81,1951.2 3275.68,1951.2 3387.15,1839.72 3458.77,1768.11 3737.78,1768.11 3774.74,1731.15 3774.74,1704.74 3865.17,1614.3 4185.56,1614.3 4197.19,1625.93 4455.54,1625.93 4475.87,1605.6 4488.71,1605.6 4509.04,1625.93 4583.19,1625.93 4589.53,1632.27 4712.24,1632.27 4721.01,1623.5 4721.01,1572.82 4731.08,1562.74 4743.43,1562.74 4753,1553.17 4753,1540.82 4762.58,1531.25 4964.85,1531.25 4973.48,1539.87 4973.48,1563.24 v1(4988.98,1578.74)
  Bottom Layer w8: J41.15@1632.61,2536.06 1700.49,2468.19 v1(1869,2468.19) ; v1@1876.56,2463.87 1883.94,2463.87 1884,2463.81 U24.9@1884,2456.06
GPIO15_FPGA: J29.H20 U24.4 | length 5002.6
  L16 PWR/SIG w5: v1(1869,2365.04) 1869,2376.74 1901.07,2408.82 1937.86,2408.82 1953.36,2424.32 1981.29,2424.32 2201.51,2204.1 2581.45,2204.1 2624.15,2161.4 2624.15,2055.55 2663.89,2015.81 3414.01,2015.81 3469.19,1960.62 3469.19,1886.36 3496,1859.55 3869.07,1859.55 3961.25,1951.73 4204.56,1951.73 4238.02,1918.27 4671.23,1918.27 4709.63,1879.87 5020.99,1879.87 5048.59,1852.27 5314.23,1852.27 5496,1670.5 5496,1282.11 5571.34,1206.77 5619.71,1206.77 5635.92,1222.98 5635.92,1382.27 5651.42,1397.77 5695.92,1397.77 v1(5711.42,1382.27)
  Bottom Layer w8: v1(1869,2365.04) 1884,2380.04 U24.4@1884,2393.07 U24.4@1884,2395.04
GPIO16_ADC: J42.1 U1.D2 U22.12 | length 4344.1
  L16 PWR/SIG w4: 4753.5,1623.26 4753.5,1572.53 4763.29,1562.74 4941.48,1562.74 v1(4957.48,1578.74)
  L16 PWR/SIG w5: v1(2346.25,2486.06) 2314.61,2454.42 2276.41,2454.42 2246.8,2424.81 2169.91,2424.81 2151.78,2442.94 2091.69,2442.94 2073.56,2424.81 2003.76,2424.81 1985.89,2442.69 1973.45,2442.69 1973.2,2442.94 1918.45,2442.94 1849.16,2373.65 1849.16,2258.09 1898.39,2208.85 1898.39,2188.22 2041.75,2044.86 2090,2044.86 2156.86,2111.73 2265.25,2111.73 2365.98,2011 2583.74,2011 2634.54,1960.2 3279.4,1960.2 3462.5,1777.11 3741.51,1777.11 3815.12,1703.5 3877.57,1703.5 3932.81,1648.27 4093.13,1648.27 4118.09,1623.3 4177.23,1623.3 4193.93,1640 4542.64,1640 4576.75,1674.12 4582.24,1674.12 4589.53,1681.4 4624.17,1681.4 4646.26,1659.31 4726.46,1659.31 4753.5,1632.27 4753.5,1623.26
  Bottom Layer w8: U22.12@2331.25,2456.06 2331.25,2471.06 v1(2346.25,2486.06) 2368.28,2508.1 2368.28,2521.72 J42.1@2382.63,2536.06
GPIO16_FPGA: J29.J18 U22.1 | length 3889.1
  L16 PWR/SIG w5: v1(2346.25,2365.04) 2348.1,2363.18 3001.23,2363.18 3040,2324.42 3040,2308.92 3130.6,2218.32 3165.37,2218.32 3165.98,2217.71 3188.32,2217.71 3189.32,2218.71 3211.65,2218.71 3212.04,2218.32 3282.82,2218.32 3291.17,2226.67 3839.25,2226.67 3854.43,2211.49 3854.43,2194.5 3877.54,2171.39 4076.16,2171.39 4090.71,2185.93 4269.54,2185.93 4306.17,2149.3 4448.99,2149.3 4490.01,2108.27 4648.01,2108.27 4662.35,2093.93 4720.29,2093.93 4733.83,2107.47 4742.83,2116.47 5034.07,2116.47 5071.54,2079 5221.54,2079 5568.27,1732.27 5568.27,1536.68 5589.2,1515.75 5627.94,1515.75 v1(5661.42,1482.27)
  Bottom Layer w8: U22.1@2331.25,2395.04 2331.25,2380.04 v1(2346.25,2365.04)
GPIO17_ADC: J42.3 U1.K16 U22.11 | length 3382.4
  L12 SIGNAL w4: 4724.31,1154.29 4752.01,1154.29 v1(4768.5,1137.8)
  L12 SIGNAL w5: v1(2315.5,2485.38) 2346.25,2454.63 2346.25,2403.75 2374.87,2375.13 2374.87,2350 2347.59,2322.72 2347.59,2248.17 2464,2131.76 2464,2065.94 2745.85,1784.09 3718.35,1784.09 3808.75,1693.69 3883.45,1693.69 3962.33,1614.81 3990.45,1614.81 4066.87,1538.39 4066.87,1507.32 4179.47,1394.71 4200.6,1394.71 4213.81,1381.5 4213.81,1356.02 4239.58,1330.25 4239.58,1212.08 4260.49,1191.18 4278.9,1191.18 4308.21,1161.87 4541.37,1161.87 4549.45,1153.79 4711.93,1153.79 4712.43,1154.29 4724.31,1154.29
  Bottom Layer w8: U22.11@2315.5,2456.06 v1(2315.5,2485.38) 2315.5,2514.7 2332.63,2531.83 J42.3@2332.63,2536.06
GPIO17_FPGA: J29.J19 U22.2 | length 4016.8
  L16 PWR/SIG w5: v1(2320.5,2360.04) 2323.37,2357.17 2330.78,2357.17 2339.41,2348.54 2353.08,2348.54 2358.73,2354.18 2997.51,2354.18 3031,2320.69 3031,2305.19 3187.41,2148.79 3240.92,2148.79 3285.82,2193.68 3285.82,2208.59 3294.9,2217.67 3727.03,2217.67 3805.42,2139.27 3988.21,2139.27 3998.21,2129.27 4063.36,2129.27 4098.7,2093.93 4264.81,2093.93 4311.17,2140.3 4445.26,2140.3 4486.29,2099.27 4644.28,2099.27 4658.62,2084.93 4724.02,2084.93 4737.56,2098.47 4746.56,2107.47 5030.35,2107.47 5067.82,2070 5217.81,2070 5559.27,1728.54 5559.27,1532.95 5581.37,1510.85 5585.74,1506.48 5613.87,1506.48 5661.42,1458.93 v1(5661.42,1432.27)
  Bottom Layer w8: v1@2315.5,2368.28 U22.2@2315.5,2393.07
GPIO18_ADC: J42.5 U1.L16 U22.10 | length 3392
  L12 SIGNAL w5: v1(2299.75,2431.06) 2249.79,2381.09 2249.79,2333.24 2455,2128.03 2455,2062.21 2742.13,1775.09 3714.62,1775.09 3883.22,1606.49 3887.37,1606.49 3887.69,1606.81 3901.35,1606.81 3902.35,1605.81 3986.72,1605.81 4057.87,1534.66 4057.87,1490.79 4230.58,1318.08 4230.58,1166.07 4262.9,1133.76 4350.27,1133.76 4364.8,1148.29 4434.47,1148.29 4460.46,1122.3 4650.52,1122.3 4651.15,1121.66 4667.46,1121.66 4667.6,1121.8 4711.44,1121.8 4727.43,1137.8 v1(4737.01,1137.8)
  Bottom Layer w8: J42.5@2282.63,2536.06 2282.63,2497.89 2288.44,2492.08 2288.44,2486.99 2299.75,2475.67 U22.10@2299.75,2456.06 v1(2299.75,2431.06)
GPIO18_FPGA: J29.J21 U22.3 | length 4229.4
  L16 PWR/SIG w5: v1(2294.75,2360.04) 2318.79,2336 2528.73,2336 2537.91,2345.18 2993.78,2345.18 3022,2316.96 3022,2301.47 3183.68,2139.79 3248.22,2139.79 3286.61,2178.17 3323.03,2178.17 3339.97,2161.23 3770.74,2161.23 3854.17,2077.8 4261.4,2077.8 4314.9,2131.3 4441.53,2131.3 4482.56,2090.27 4640.55,2090.27 4654.89,2075.93 4727.75,2075.93 4741.29,2089.47 4750.29,2098.47 5026.62,2098.47 5064.09,2061 5214.08,2061 5550,1725.08 5550,1521.77 5607.44,1464.33 5624.17,1464.33 5644.92,1443.58 5644.92,1425.43 5654.58,1415.77 5723.69,1415.77 5738.85,1400.61 5738.85,1372.97 5715.15,1349.27 5678.42,1349.27 v1(5661.42,1332.27)
  Bottom Layer w8: v1@2299.75,2368.28 U22.3@2299.75,2393.07
GPIO19_ADC: J42.7 U1.J17 U22.9 | length 5095.2
  L16 PWR/SIG w4: 4831.5,1500.25 4832.49,1499.25 4837.71,1499.25 4846.5,1490.46 4846.5,1327.1 4847,1326.6
  L16 PWR/SIG w5: v1(2269.01,2486.06) 2240.79,2457.84 2235.99,2457.84 2220.84,2442.69 2164.76,2442.69 2151.64,2455.81 2020.86,2455.81 2002.99,2473.69 1973.45,2473.69 1951.7,2451.94 1908.58,2451.94 1875.84,2484.69 1836.52,2484.69 1824.27,2472.44 1824.27,2257.51 1880.39,2201.4 1880.39,2180.77 2034.29,2026.86 2097.45,2026.86 2164.32,2093.73 2255.21,2093.73 2355.94,1993 2576.29,1993 2627.08,1942.2 3271.95,1942.2 3455.04,1759.11 3734.06,1759.11 3765.74,1727.43 3765.74,1658.99 3849.92,1574.81 4490.66,1574.81 4510.09,1594.24 4680.44,1594.24 4690,1584.68 4690,1572.34 4699.56,1562.77 4711.9,1562.77 4721.45,1553.23 4721.45,1540.89 4730.96,1531.37 4743.3,1531.37 4752.76,1521.92 4752.76,1509.58 4762.08,1500.25 4831.5,1500.25 ; v1(4800,1106.3) 4816.01,1090.29 5001.15,1090.29 5035.97,1125.11 5035.97,1270.85 5027.54,1279.28 4887.73,1279.28 4878.49,1288.52 4878.49,1301.7 4869.41,1310.78 4856.24,1310.78 4847,1320.02 4847,1326.6
  Bottom Layer w8: J42.7@2232.63,2536.06 2239.01,2529.68 2239.01,2516.06 v1(2269.01,2486.06) 2284.01,2471.06 U22.9@2284.01,2456.06
GPIO19_FPGA: J29.J22 U22.4 | length 4353.3
  L16 PWR/SIG w5: v1(2269.01,2365.04) 2269.01,2346.25 2288.25,2327 2525,2327 2666.69,2185.31 2720.42,2185.31 2761.36,2144.36 2780.03,2125.69 3008.96,2125.69 3066.38,2068.27 3365.6,2068.27 3449.56,2152.23 3767.01,2152.23 3850.45,2068.8 4265.13,2068.8 4315.74,2119.41 4434.3,2119.41 4472.44,2081.27 4636.83,2081.27 4651.16,2066.93 4731.48,2066.93 4754.01,2089.47 5022.89,2089.47 5060.36,2052 5210.36,2052 5541,1721.36 5541,1518.04 5603.71,1455.33 5620.44,1455.33 5635.92,1439.86 5635.92,1421.71 5650.86,1406.77 5719.96,1406.77 5729.85,1396.88 5729.85,1376.7 5711.42,1358.27 5664.08,1358.27 5644.92,1339.1 5644.92,1325.43 5661.42,1308.93 v1(5661.42,1282.27)
  Bottom Layer w8: v1(2269.01,2365.04) 2284.01,2380.04 U22.4@2284.01,2393.07 U22.4@2284.01,2395.04
GPIO20_ADC: J42.9 U1.K17 U25.12 | length 3908
  L12 SIGNAL w4: 2087.26,2510.8 2092.38,2510.8 2107.86,2526.28 2107.86,2546.32 2122.37,2560.82 2142.88,2560.82 2157.39,2546.32 2157.39,2545.22 2159.73,2542.88 2175.81,2542.88 J42.9@2182.63,2536.06
  L12 SIGNAL w5: 2087.26,2510.8 2058.83,2510.8 2003.76,2455.73 2003.76,2423.51 2050,2377.28 2050,2350 2288.82,2111.18 2353.82,2111.18 2509.19,1955.81 2509.19,1935.51 2687.61,1757.09 3693.91,1757.09 3791,1660 3791,1636.27 3867.27,1560 4007.07,1560 4039.87,1527.21 4039.87,1483.34 4212.58,1310.62 4212.58,1158.62 4255.44,1115.76 4367.09,1115.76 4452.11,1030.74 4692.94,1030.74 v1(4768.5,1106.3)
  Bottom Layer w8: U25.12@2131.25,2456.06 2131.25,2471.06 2176.25,2516.06 2176.25,2529.68 J42.9@2182.63,2536.06
GPIO20_FPGA: J29.K19 U25.1 | length 4072.3
  L16 PWR/SIG w5: v1(2146.25,2365.04) 2271.19,2240.1 2597.45,2240.1 2634.05,2203.49 2634.05,2202.4 2660.15,2176.31 2716.69,2176.31 2781.27,2111.73 3010.2,2111.73 3062.65,2059.27 3562.29,2059.27 3569.21,2066.19 3583.14,2066.19 3593.89,2076.94 3610.82,2076.94 3611.64,2077.77 3624.48,2077.77 3625.3,2076.94 3677.48,2076.94 3694.63,2059.8 4268.86,2059.8 4319.47,2110.41 4423.33,2110.41 4495.08,2038.66 4671.91,2038.66 4679.16,2045.91 4692,2045.91 4699.25,2038.66 5012.13,2038.66 5121.46,1929.33 5320.3,1929.33 5532,1717.63 5532,1511.69 v1(5611.42,1432.27)
  Bottom Layer w8: U25.1@2131.25,2395.04 2131.25,2380.04 v1(2146.25,2365.04)
GPIO21_ADC: J42.11 U1.L17 U25.11 | length 3552.2
  L12 SIGNAL w5: v1(2124.87,2497.89) 2124.87,2449.36 2140.37,2433.86 2140.37,2406.39 2183.91,2362.85 2183.91,2228.82 2292.55,2120.18 2357.82,2120.18 2518.19,1959.81 2518.19,1939.24 2691.34,1766.09 3697.64,1766.09 3800,1663.73 3800,1650 3800,1640 3871,1569 4000.96,1569 4010.8,1569 4048.87,1530.93 4048.87,1487.06 4221.58,1314.35 4221.58,1162.34 4259.17,1124.76 4371.4,1124.76 4405.36,1090.8 4721.51,1090.8 v1(4737.01,1106.3)
  Bottom Layer w8: U25.11@2115.5,2456.06 2115.5,2487.2 2124.87,2496.57 v1(2124.87,2497.89) 2124.87,2501.14 2129.91,2506.18 2129.91,2533.34 J42.11@2132.62,2536.06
